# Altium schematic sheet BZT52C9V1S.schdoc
size 127 x 101 mm
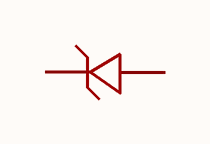
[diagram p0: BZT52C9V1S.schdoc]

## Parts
ZD?  bzt52c9v1s_c22614  [SOD-323_L1.8-W1.3-LS2.5-RD]  (value not drawn)

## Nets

Not connected (* = marked no-connect by the designer): ZD? 1(K) 2(A)

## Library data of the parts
ZD? = bzt52c9v1s_c22614: 二极管配置:1个独立式;稳压值(标称值):9.1V;稳压值(范围值):8.5V~9.6V;耗散功率(Pd):200mW;; Manufacturer: CJ(江苏长电/长晶); AddInBom: yes; ModelId: db63db13d9e342eb939127d413d6200b; ModelTransform: 104.3305,51.181,0,0,0,0,0,-0.004,0; Diode Configuration: 1个独立式; Zener Voltage(Nom): 9.1V; Reverse Leakage Current (Ir): 500nA@6V; Pd - Power Dissipation: 200mW; Impedance(Zzt): 15Ω; Impedance(Zzk): 100Ω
